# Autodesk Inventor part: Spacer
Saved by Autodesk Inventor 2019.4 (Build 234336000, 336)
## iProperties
Created: 2020-04
Part Number: Spacer
Material: Generic
Document SubType Name: Modeling
Designer: Administrator
Density: 1 g/cm^3
Appearance: Default
Title: Spacer v9
Author: Administrator
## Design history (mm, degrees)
feature "Body1"
feature "Body2"
feature "Body3"
feature "Body4"
body "Solid1"
body "Solid2"
body "Solid3"
body "Solid4"
